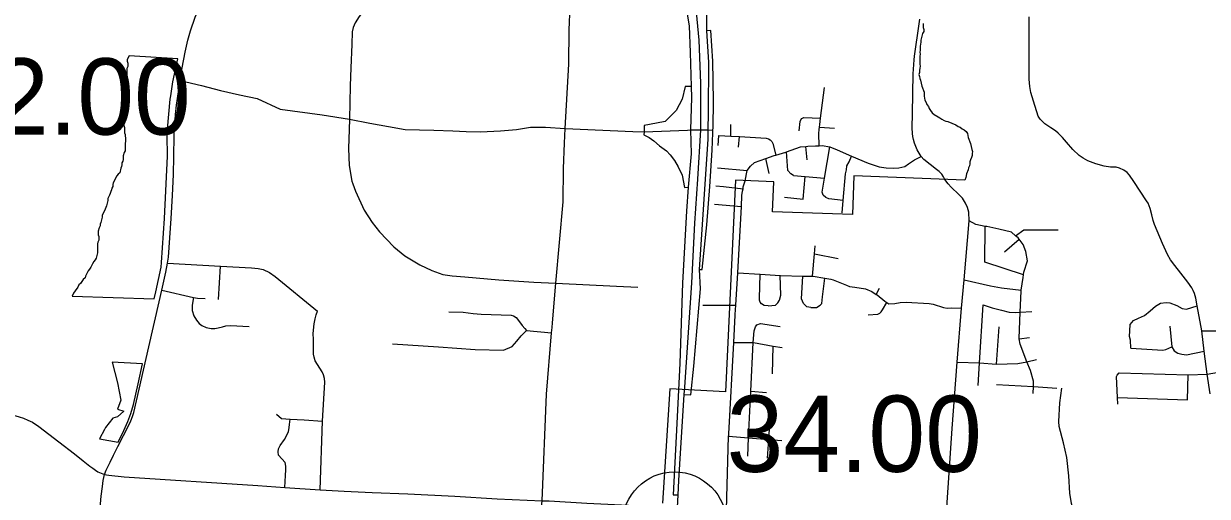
# Model space of a CAD drawing. Extents: x 1729596 to 1934326, y 644115 to 911751.
# Drawn here: x 1846156 to 1863218, y 740936 to 747751 of the extents above; entities that cross this region are included whole.
import ezdxf

# ---------------------------------------------------------------- set-up
doc = ezdxf.new("R2010")
doc.units = 0
for name, color, linetype in [('Default', 7, 'Continuous'), ('GM_X_City_Street', 7, 'Continuous'), ('GM_X_Corporation', 7, 'Continuous'), ('GM_X_Interchange_Ramps', 7, 'Continuous'), ('GM_X_Interstate_Route', 7, 'Continuous')]:
    doc.layers.add(name, color=color, linetype=linetype)

msp = doc.modelspace()

# ---------------------------------------------------------------- linework, layer by layer
at = {"layer": 'Default'}
msp.add_circle((1855538, 740539), 750, dxfattribs=at)
at = {"layer": 'GM_X_City_Street'}
for points in [[(1848441, 747114), (1848484, 747338), (1848524, 747512), (1848562, 747647), (1848628, 747845), (1848787, 748202), (1848917, 748476), (1849003, 748646), (1849050, 748739), (1849112, 748844), (1849162, 748916), (1849207, 748970), (1849269, 749035), (1849313, 749075), (1849390, 749136), (1849511, 749223), (1849637, 749311), (1849760, 749396), (1849870, 749490), (1849948, 749568), (1850121, 749810), (1850178, 749898)], [(1851432, 749838), (1851405, 749428), (1851356, 749164), (1851343, 748864), (1851333, 748672), (1851315, 748559), (1851290, 748415), (1851241, 748265), (1851165, 748123), (1851097, 748013), (1851039, 747917), (1850993, 747855), (1850933, 747761), (1850903, 747696), (1850893, 747632), (1850888, 747450), (1850873, 747113), (1850864, 746855), (1850853, 746374), (1850846, 746224), (1850838, 745952), (1850846, 745706), (1850886, 745480), (1850900, 745441)], [(1853953, 746027), (1853963, 746238), (1854012, 747167), (1854020, 747660), (1854033, 747996), (1854028, 748094), (1854012, 748171), (1853967, 748271), (1853922, 748347)], [(1863260, 742415), (1863215, 742698), (1863171, 743028), (1863137, 743322), (1863073, 743681), (1863050, 743795), (1863033, 743859), (1863015, 743904), (1862994, 743943), (1862939, 744025), (1862837, 744155), (1862750, 744264), (1862689, 744344), (1862645, 744421), (1862570, 744581), (1862456, 744854), (1862435, 744915), (1862416, 744994), (1862393, 745088), (1862364, 745161), (1862343, 745198), (1862160, 745477), (1862097, 745566), (1862062, 745606), (1862014, 745638), (1861954, 745668), (1861905, 745680), (1861824, 745684), (1861731, 745697), (1861609, 745731), (1861497, 745774), (1861426, 745810), (1861371, 745850), (1861278, 745937), (1861188, 746043), (1861130, 746110), (1861066, 746170), (1861027, 746207), (1860960, 746250), (1860875, 746305), (1860806, 746374), (1860777, 746417), (1860711, 746634), (1860675, 746758), (1860659, 746845), (1860651, 746952), (1860648, 747203), (1860649, 747307), (1860648, 747687), (1860652, 747847)], [(1859414, 745541), (1859391, 745580), (1859351, 745617), (1859314, 745648), (1859130, 745793), (1859094, 745835), (1859037, 745932), (1858996, 746029), (1858982, 746081), (1858972, 746122), (1858966, 746166), (1858964, 746250), (1858967, 746454), (1858979, 747027), (1858993, 747230), (1858999, 747280), (1859010, 747385), (1859050, 747649), (1859073, 747815)], [(1847251, 740663), (1847273, 740937), (1847291, 741079), (1847301, 741162), (1847322, 741252), (1847344, 741311), (1847401, 741429), (1847450, 741530), (1847513, 741656), (1847675, 741970), (1847701, 742024), (1847725, 742086), (1847746, 742145), (1847960, 743090), (1848107, 743739), (1848145, 743909), (1848203, 744170), (1848231, 744296), (1848243, 744383), (1848281, 744940), (1848301, 745273), (1848315, 745577), (1848319, 745834), (1848326, 746134), (1848330, 746263), (1848338, 746366), (1848343, 746441), (1848360, 746574), (1848373, 746674), (1848412, 746932), (1848425, 747012), (1848436, 747085), (1848441, 747114)], [(1848412, 746932), (1848719, 746861), (1848991, 746789), (1849267, 746725), (1849521, 746672), (1849851, 746516), (1850457, 746434), (1850853, 746374)], [(1857621, 745991), (1857620, 746166), (1857622, 746226), (1857627, 746260), (1857632, 746296), (1857644, 746389), (1857701, 746830)], [(1850853, 746374), (1850853, 746374), (1851145, 746317), (1851415, 746266), (1851655, 746227), (1852069, 746217), (1852341, 746206), (1852536, 746198)], [(1856347, 746129), (1856350, 746296)], [(1857335, 746206), (1857350, 746338), (1857360, 746364), (1857372, 746384), (1857402, 746400), (1857644, 746389)], [(1852536, 746198), (1852740, 746189), (1853029, 746206), (1853260, 746227), (1853463, 746260), (1853677, 746260), (1853963, 746238)], [(1853963, 746238), (1854936, 746198)], [(1854936, 746198), (1855098, 746191), (1855726, 746216)], [(1855726, 746216), (1855767, 746218), (1855910, 746218), (1856024, 746218), (1856092, 746215)], [(1856169, 745995), (1856177, 746139)], [(1856177, 746139), (1856347, 746129), (1856473, 746122), (1856858, 746100), (1856891, 746090), (1856914, 746075), (1856939, 746050), (1856954, 746022), (1856996, 745857)], [(1857627, 746260), (1857844, 746243)], [(1853773, 743370), (1853778, 743438), (1853828, 744008), (1853931, 745184), (1853937, 745663), (1853953, 746027)], [(1856459, 745972), (1856473, 746122)], [(1856585, 745634), (1856633, 745698), (1856690, 745748), (1856852, 745806), (1856974, 745851), (1856996, 745857), (1857140, 745899), (1857154, 745904), (1857352, 745977), (1857428, 745982), (1857460, 745983), (1857570, 745988), (1857608, 745990)], [(1857449, 745789), (1857428, 745982)], [(1857608, 745990), (1857621, 745991), (1857668, 745994), (1857777, 745975), (1857880, 745934), (1858088, 745841), (1858331, 745738), (1858487, 745688), (1858589, 745672), (1858693, 745667), (1858773, 745673), (1858855, 745689), (1858909, 745729), (1858995, 745789), (1859094, 745835)], [(1857970, 745203), (1857760, 745226), (1857718, 745246), (1857682, 745278), (1857667, 745322), (1857701, 745522), (1857777, 745975)], [(1856901, 745591), (1856852, 745806)], [(1857253, 745560), (1857213, 745588), (1857171, 745634), (1857154, 745904)], [(1857954, 745022), (1857970, 745203), (1858003, 745585), (1858015, 745644), (1858019, 745702), (1858053, 745758), (1858088, 745841)], [(1856158, 745671), (1856585, 745634)], [(1856555, 745483), (1856585, 745634)], [(1856414, 743558), (1856422, 743690), (1856448, 744159), (1856501, 745114), (1856509, 745271), (1856519, 745337), (1856525, 745371), (1856529, 745397), (1856555, 745483)], [(1857125, 745248), (1857390, 745222), (1857423, 745546)], [(1857253, 745560), (1857423, 745546), (1857701, 745522)], [(1859446, 740562), (1859446, 740562), (1859538, 741913), (1859613, 742871), (1859673, 743650), (1859714, 744057), (1859786, 744910), (1859781, 745031), (1859762, 745100), (1859733, 745161), (1859689, 745234), (1859635, 745289), (1859523, 745393), (1859483, 745442), (1859436, 745505), (1859414, 745541)], [(1850900, 745441), (1850937, 745334), (1851066, 745064), (1851177, 744886), (1851284, 744751), (1851491, 744532), (1851651, 744403), (1851868, 744273), (1852041, 744191), (1852199, 744133), (1852332, 744114), (1852515, 744099), (1853004, 744057), (1853508, 744024), (1853828, 744008)], [(1856134, 745415), (1856245, 745405), (1856525, 745371)], [(1856116, 745146), (1856501, 745114)], [(1860709, 742420), (1860710, 742518), (1860712, 742596), (1860667, 742752), (1860616, 742877), (1860518, 743132), (1860507, 743205), (1860506, 743212), (1860522, 743593), (1860534, 743892), (1860536, 743906), (1860563, 744090), (1860568, 744130), (1860573, 744168), (1860624, 744329), (1860602, 744465), (1860563, 744565), (1860507, 744642), (1860491, 744663), (1860455, 744694), (1860393, 744747), (1860213, 744788), (1860037, 744824), (1860013, 744828), (1859883, 744853), (1859786, 744910)], [(1860568, 744130), (1860012, 744313), (1860013, 744828)], [(1860455, 744694), (1860573, 744778), (1861069, 744777)], [(1860292, 744460), (1860507, 744642)], [(1857528, 744108), (1857555, 744431), (1857564, 744547)], [(1857555, 744431), (1857895, 744364)], [(1848231, 744296), (1848991, 744255), (1849442, 744232), (1849538, 744219), (1849609, 744204), (1849697, 744163), (1849780, 744106), (1850391, 743604)], [(1848962, 743775), (1848991, 744255)], [(1856448, 744159), (1856774, 744138), (1857062, 744119), (1857066, 744119), (1857386, 744112), (1857528, 744108), (1857534, 744108), (1857703, 744082), (1857790, 744069), (1857826, 744057), (1858016, 743980), (1858062, 743960), (1858136, 743950), (1858292, 743928), (1858384, 743889), (1858445, 743848), (1858458, 743839), (1858571, 743749), (1858597, 743732), (1858625, 743713), (1858713, 743716), (1858791, 743732), (1858875, 743736), (1859209, 743717), (1859267, 743707), (1859413, 743658), (1859469, 743648), (1859527, 743654), (1859673, 743650)], [(1856885, 743683), (1856831, 743685), (1856793, 743711), (1856771, 743733), (1856763, 743765), (1856763, 743789), (1856774, 744138)], [(1856885, 743683), (1856991, 743692), (1857027, 743724), (1857053, 743766), (1857071, 743836), (1857062, 744119)], [(1857501, 743657), (1857447, 743667), (1857395, 743717), (1857367, 743785), (1857386, 744112)], [(1857501, 743657), (1857583, 743658), (1857639, 743694), (1857659, 743718), (1857669, 743810), (1857703, 744082)], [(1848145, 743909), (1848603, 743805), (1848663, 743794), (1848774, 743790)], [(1853828, 744008), (1854702, 743965)], [(1854702, 743965), (1855010, 743950)], [(1858445, 743848), (1858493, 743936)], [(1859714, 744057), (1860090, 743970), (1860250, 743943), (1860536, 743906)], [(1848603, 743805), (1848583, 743691), (1848586, 743614), (1848607, 743540), (1848645, 743476), (1848686, 743429), (1848725, 743399), (1848788, 743369), (1848857, 743354), (1848912, 743356), (1848959, 743367), (1849022, 743381), (1849071, 743396), (1849139, 743398), (1849406, 743386)], [(1850431, 741032), (1850464, 742021), (1850498, 742580), (1850490, 742634), (1850477, 742690), (1850459, 742729), (1850357, 742889), (1850343, 742941), (1850335, 742985), (1850335, 743070), (1850334, 743196), (1850330, 743284), (1850342, 743424), (1850356, 743496), (1850371, 743552), (1850391, 743604)], [(1852286, 743598), (1852492, 743593), (1852637, 743572), (1852752, 743560), (1853185, 743547), (1853218, 743536), (1853255, 743513), (1853303, 743453), (1853343, 743397), (1853381, 743355), (1853405, 743326), (1853766, 743292)], [(1855945, 743692), (1856422, 743690)], [(1858329, 743552), (1858469, 743560), (1858495, 743577), (1858517, 743597), (1858537, 743627), (1858597, 743732)], [(1859935, 742859), (1859986, 743696), (1860117, 743654), (1860251, 743620), (1860359, 743593), (1860455, 743585), (1860522, 743593)], [(1860522, 743593), (1860687, 743602)], [(1862155, 743472), (1862225, 743503), (1862314, 743543), (1862392, 743609), (1862470, 743678), (1862542, 743722), (1862624, 743732), (1862678, 743725), (1862780, 743687), (1862856, 743645), (1862918, 743635), (1863073, 743681)], [(1856319, 741836), (1856392, 743152), (1856414, 743547), (1856414, 743558)], [(1856673, 743152), (1856684, 743322), (1856706, 743382), (1856724, 743408), (1856778, 743429), (1857060, 743383)], [(1862116, 743070), (1862108, 743186), (1862098, 743238), (1862099, 743324), (1862107, 743412), (1862155, 743472)], [(1851473, 743134), (1852135, 743093), (1852666, 743051), (1853070, 743043), (1853197, 743098), (1853265, 743175), (1853327, 743252), (1853405, 743326)], [(1853600, 740609), (1853629, 740869), (1853691, 742408), (1853766, 743292), (1853773, 743370)], [(1860177, 742843), (1860218, 743378)], [(1860507, 743205), (1860654, 743227)], [(1862675, 743390), (1862704, 743091), (1862742, 743036), (1862792, 743000), (1862850, 742986), (1862916, 742978), (1863171, 743028)], [(1863137, 743322), (1863488, 743324), (1863575, 743321), (1863631, 743322), (1863667, 743306), (1863739, 743271), (1863950, 743139), (1863978, 743125), (1864028, 743108), (1864090, 743100), (1864111, 743097), (1864165, 743091), (1864562, 743057), (1864991, 743021)], [(1856392, 743152), (1856673, 743152), (1856677, 743152), (1856960, 743103), (1857089, 743081)], [(1856606, 741780), (1856639, 742451), (1856673, 743152)], [(1856948, 742704), (1856960, 743103)], [(1862116, 743070), (1862576, 743043), (1862618, 743055), (1862704, 743091)], [(1859613, 742871), (1859935, 742859), (1860177, 742843), (1860181, 742843), (1860487, 742850), (1860616, 742877), (1860755, 742907)], [(1859916, 742533), (1859935, 742859)], [(1861919, 742682), (1861949, 742716), (1862941, 742689), (1863215, 742698)], [(1863215, 742698), (1863410, 742730), (1863462, 742729), (1863665, 742718), (1863776, 742687), (1863846, 742638), (1863882, 742568), (1863893, 742485), (1863887, 742438), (1863866, 742396)], [(1860180, 742546), (1860710, 742518)], [(1861927, 742267), (1861922, 742361), (1861907, 742664), (1861919, 742682)], [(1861922, 742361), (1862934, 742327), (1862941, 742689)], [(1856639, 742451), (1856861, 742435)], [(1860710, 742518), (1861050, 742497)], [(1861900, 739635), (1861900, 739643), (1861901, 739749), (1861886, 739801), (1861849, 739870), (1861717, 740052), (1861565, 740301), (1861431, 740522), (1861291, 740735), (1861262, 740833), (1861237, 740980), (1861221, 741231), (1861192, 741496), (1861144, 741709), (1861082, 741942), (1861075, 742015), (1861090, 742283), (1861121, 742497)], [(1856879, 741485), (1856895, 741754), (1856924, 742211)], [(1845794, 742123), (1845851, 742120), (1845942, 742112), (1845987, 742106), (1846042, 742096), (1846093, 742084), (1846151, 742064), (1846218, 742036), (1846281, 742003), (1846374, 741942), (1846662, 741724), (1846888, 741547)], [(1849801, 742119), (1849873, 742057), (1849997, 742049), (1850200, 742037)], [(1849922, 741065), (1849932, 741235), (1849935, 741319), (1849935, 741373), (1849925, 741423), (1849830, 741530), (1849824, 741578), (1849830, 741622), (1849854, 741668), (1849916, 741756), (1849971, 741868), (1849983, 741928), (1849987, 741972), (1849997, 742049)], [(1850200, 742037), (1850200, 742037), (1850464, 742021)], [(1856289, 740739), (1856317, 741802), (1856318, 741818), (1856319, 741836)], [(1856317, 741802), (1856605, 741778), (1856895, 741754), (1857086, 741739)], [(1856593, 741517), (1856605, 741778), (1856606, 741780)], [(1846888, 741547), (1847011, 741450), (1847110, 741373), (1847151, 741341), (1847189, 741314), (1847226, 741290), (1847322, 741252)], [(1847322, 741252), (1847351, 741244), (1847382, 741240), (1847603, 741215), (1849529, 741091), (1849922, 741065), (1850431, 741032), (1850777, 741011), (1851179, 740992), (1851693, 740972), (1852369, 740936), (1852982, 740899), (1853629, 740869), (1853731, 740873), (1854275, 740839), (1855574, 740776), (1855703, 740770)]]:
    msp.add_lwpolyline(points, dxfattribs=at)
at = {"layer": 'GM_X_Corporation'}
msp.add_lwpolyline([(1859124, 747753), (1859124, 747695), (1859130, 747667), (1859130, 747638), (1859112, 747609), (1859101, 747569), (1859090, 747512), (1859090, 747483), (1859078, 747426), (1859078, 747369), (1859072, 747340), (1859078, 747312), (1859072, 747283), (1859072, 747168), (1859078, 747140), (1859072, 747111), (1859067, 747077), (1859067, 747048), (1859061, 747019), (1859067, 746991), (1859072, 746962), (1859084, 746934), (1859101, 746848), (1859135, 746762), (1859135, 746704), (1859147, 746647), (1859164, 746613), (1859175, 746584), (1859198, 746556), (1859210, 746527), (1859227, 746498), (1859250, 746464), (1859278, 746441), (1859336, 746407), (1859364, 746395), (1859393, 746372), (1859422, 746355), (1859450, 746344), (1859479, 746338), (1859593, 746292), (1859628, 746269), (1859656, 746258), (1859685, 746235), (1859714, 746218), (1859742, 746195), (1859759, 746166), (1859771, 746109), (1859805, 746023), (1859822, 745937), (1859834, 745908), (1859828, 745880), (1859828, 745851), (1859817, 745823), (1859805, 745788), (1859794, 745760), (1859794, 745731), (1859788, 745702), (1859777, 745674), (1859771, 745645), (1859748, 745588), (1859737, 745531), (1859723, 745496), (1858122, 745556), (1858101, 744997), (1856952, 745040), (1856968, 745471), (1856418, 745492), (1856271, 742445), (1855472, 742484), (1855362, 740838)], dxfattribs=at)
for points in [[(1846853, 743820), (1848035, 743785), (1848059, 743884), (1848138, 744241), (1848143, 744306), (1848186, 744944), (1848231, 745840), (1848225, 746136), (1848227, 746228), (1848267, 746663), (1848275, 746711), (1848306, 746912), (1848377, 747244), (1847676, 747286), (1847649, 747233), (1847649, 747208), (1847656, 747182), (1847656, 747131), (1847643, 747106), (1847643, 747004), (1847637, 746979), (1847649, 746954), (1847656, 746928), (1847656, 746878), (1847649, 746846), (1847649, 746820), (1847656, 746795), (1847656, 746770), (1847662, 746744), (1847662, 746643), (1847637, 746541), (1847630, 746516), (1847630, 746459), (1847624, 746433), (1847611, 746408), (1847611, 746383), (1847605, 746357), (1847605, 746332), (1847598, 746306), (1847598, 746281), (1847611, 746256), (1847611, 746179), (1847617, 746154), (1847617, 746129), (1847624, 746103), (1847624, 746053), (1847617, 746027), (1847617, 745919), (1847605, 745894), (1847592, 745843), (1847592, 745792), (1847586, 745767), (1847573, 745742), (1847573, 745716), (1847567, 745691), (1847554, 745665), (1847541, 745602), (1847516, 745583), (1847497, 745558), (1847446, 745456), (1847440, 745431), (1847440, 745405), (1847427, 745380), (1847421, 745354), (1847414, 745329), (1847402, 745304), (1847395, 745278), (1847370, 745228), (1847370, 745202), (1847351, 745126), (1847338, 745101), (1847332, 745075), (1847287, 744986), (1847287, 744961), (1847268, 744885), (1847256, 744860), (1847256, 744834), (1847243, 744809), (1847230, 744758), (1847230, 744707), (1847237, 744682), (1847237, 744631), (1847224, 744599), (1847218, 744574), (1847218, 744447), (1847199, 744371), (1847186, 744345), (1847167, 744320), (1847148, 744288), (1847122, 744238), (1847103, 744212), (1847084, 744187), (1847046, 744111), (1847040, 744085), (1847015, 744060), (1846996, 744035), (1846977, 744003), (1846951, 743984), (1846938, 743952), (1846900, 743901), (1846875, 743863)], [(1847249, 741763), (1847520, 741715), (1847598, 741883), (1847658, 742017), (1847701, 742130), (1847738, 742260), (1847804, 742557), (1847869, 742848), (1847429, 742872), (1847508, 742572), (1847554, 742323), (1847508, 742194), (1847600, 742162), (1847510, 742081), (1847439, 742065), (1847337, 741927), (1847321, 741899)]]:
    msp.add_lwpolyline(points, close=True, dxfattribs=at)
at = {"layer": 'GM_X_Interchange_Ramps'}
for points in [[(1855643, 748349), (1855749, 747720), (1855765, 747335), (1855776, 746845), (1855782, 746684), (1855767, 746218), (1855777, 745873), (1855735, 745391), (1855708, 745046), (1855652, 744014), (1855612, 742849), (1855561, 741797), (1855519, 740960), (1855585, 740956)], [(1855672, 742403), (1855773, 742398), (1855818, 742815), (1855911, 743930), (1855899, 744206), (1856023, 746087), (1856024, 746218), (1856027, 746464), (1856034, 747197), (1856003, 747647), (1856002, 748113)], [(1856092, 746215), (1856094, 746250), (1856101, 746636), (1856091, 747210), (1856063, 747652), (1856003, 747647)], [(1855776, 746845), (1855693, 746845), (1855648, 746662), (1855559, 746500), (1855403, 746339), (1855175, 746299), (1855102, 746281), (1855098, 746191)], [(1855098, 746191), (1855096, 746149), (1855171, 746108), (1855241, 746061), (1855319, 745989), (1855421, 745919), (1855477, 745859), (1855537, 745779), (1855592, 745688), (1855646, 745568), (1855681, 745389), (1855735, 745391)], [(1855899, 744206), (1855935, 744205), (1856004, 744851), (1856048, 745401), (1856082, 745928), (1856091, 746177), (1856092, 746215)]]:
    msp.add_lwpolyline(points, dxfattribs=at)
at = {"layer": 'GM_X_Interstate_Route'}
for points in [[(1855559, 749563), (1855666, 749062), (1855743, 748680), (1855787, 748448), (1855832, 748122), (1855889, 747513), (1855913, 746894), (1855910, 746218), (1855867, 745511), (1855827, 744875), (1855781, 744012), (1855679, 742509)], [(1855679, 742509), (1855672, 742403), (1855608, 741398), (1855596, 741163)], [(1855596, 741163), (1855585, 740956), (1855574, 740776)]]:
    msp.add_lwpolyline(points, dxfattribs=at)

# ---------------------------------------------------------------- texts
at = {"layer": 'Default'}
for s, p in [('22.00', (1844884, 746151)), ('34.00', (1856288, 741289))]:
    msp.add_text(s, height=1100, dxfattribs=at).set_placement(p)

doc.saveas('drawing.dxf')
